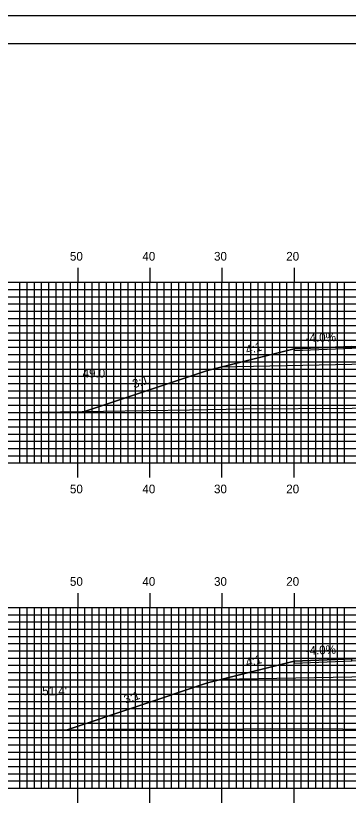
# Model space of a CAD drawing. Extents: x 1822392 to 1822735, y 442591 to 442811.
# Drawn here: x 1822499.2 to 1822545.3, y 442701.2 to 442810.5 of the extents above; entities that cross this region are included whole.
import ezdxf

# ---------------------------------------------------------------- set-up
doc = ezdxf.new("R2010")
doc.units = 0
for name, color, linetype in [('ANNOTATION', 7, 'Continuous'), ('BORDER', 7, 'Continuous'), ('D_Roadway_Centerline', 7, 'Continuous'), ('D_Roadway_Edge_Shoulder', 7, 'Continuous'), ('D_Roadway_SlopeLines', 7, 'Continuous'), ('D_Roadway_SubGrade', 7, 'Continuous'), ('D_Text_Standard', 7, 'Continuous'), ('H_V ANNOTATION', 7, 'Continuous'), ('MAJOR', 7, 'Continuous'), ('MINOR', 7, 'Continuous'), ('PLOT BOUNDARY', 7, 'Continuous'), ('S_Roadway_Centerline', 7, 'Continuous')]:
    doc.layers.add(name, color=color, linetype=linetype)

msp = doc.modelspace()

# ---------------------------------------------------------------- linework, layer by layer
at = {"layer": 'BORDER'}
msp.add_lwpolyline([(1822408.17, 442596.67), (1822728.17, 442596.67), (1822728.17, 442806.67), (1822408.17, 442806.67)], close=True, dxfattribs=at)
at = {"layer": 'D_Roadway_Centerline'}
for points in [[(1822508.73, 442755.8), (1822525.77, 442761.48), (1822527.6, 442761.94), (1822537.77, 442764.48), (1822545.77, 442764.8), (1822557.77, 442765.04), (1822569.77, 442764.8), (1822577.77, 442764.48), (1822587.94, 442761.94), (1822589.77, 442761.48), (1822605.37, 442756.28)], [(1822506.33, 442711.75), (1822525.77, 442718.23), (1822527.6, 442718.69), (1822537.77, 442721.23), (1822545.77, 442721.55), (1822557.77, 442721.79), (1822569.77, 442721.55), (1822577.77, 442721.23), (1822587.94, 442718.69), (1822589.77, 442718.23), (1822609.65, 442711.6)]]:
    msp.add_lwpolyline(points, dxfattribs=at)
at = {"layer": 'D_Roadway_Edge_Shoulder'}
for points in [[(1822545.77, 442764.8), (1822537.77, 442764.48), (1822537.77, 442764.23), (1822545.77, 442764.55)], [(1822545.77, 442721.55), (1822537.77, 442721.23), (1822537.77, 442720.98), (1822545.77, 442721.3)]]:
    msp.add_lwpolyline(points, close=True, dxfattribs=at)
at = {"layer": 'D_Roadway_SlopeLines'}
for points in [[(1822537.77, 442764.48), (1822525.77, 442761.48), (1822508.73, 442755.8)], [(1822537.77, 442721.23), (1822525.77, 442718.23), (1822506.33, 442711.75)]]:
    msp.add_lwpolyline(points, dxfattribs=at)
at = {"layer": 'D_Roadway_SubGrade'}
for points in [[(1822545.77, 442762.3), (1822527.6, 442761.94), (1822537.77, 442764.48), (1822537.77, 442764.23), (1822545.77, 442764.55), (1822557.77, 442764.79), (1822569.77, 442764.55), (1822577.77, 442764.23), (1822577.77, 442764.48), (1822587.94, 442761.94), (1822569.77, 442762.3), (1822557.77, 442762.54)], [(1822545.77, 442719.05), (1822527.6, 442718.69), (1822537.77, 442721.23), (1822537.77, 442720.98), (1822545.77, 442721.3), (1822557.77, 442721.54), (1822569.77, 442721.3), (1822577.77, 442720.98), (1822577.77, 442721.23), (1822587.94, 442718.69), (1822569.77, 442719.05), (1822557.77, 442719.29)]]:
    msp.add_lwpolyline(points, close=True, dxfattribs=at)
at = {"layer": 'MAJOR'}
for p, q in [((1822507.77, 442775.67), (1822507.77, 442773.67)), ((1822517.77, 442775.67), (1822517.77, 442773.67)), ((1822527.77, 442775.67), (1822527.77, 442773.67)), ((1822537.77, 442775.67), (1822537.77, 442773.67)), ((1822417.77, 442773.67), (1822697.77, 442773.67)), ((1822417.77, 442773.67), (1822697.77, 442773.67)), ((1822507.77, 442748.67), (1822507.77, 442773.67)), ((1822517.77, 442748.67), (1822517.77, 442773.67)), ((1822527.77, 442748.67), (1822527.77, 442773.67)), ((1822537.77, 442748.67), (1822537.77, 442773.67)), ((1822417.77, 442768.67), (1822697.77, 442768.67)), ((1822417.77, 442763.67), (1822697.77, 442763.67)), ((1822417.77, 442758.67), (1822697.77, 442758.67)), ((1822417.77, 442753.67), (1822697.77, 442753.67)), ((1822417.77, 442748.67), (1822697.77, 442748.67)), ((1822417.77, 442748.67), (1822697.77, 442748.67)), ((1822507.77, 442746.66), (1822507.77, 442748.67)), ((1822517.77, 442746.66), (1822517.77, 442748.67)), ((1822527.77, 442746.66), (1822527.77, 442748.67)), ((1822537.77, 442746.66), (1822537.77, 442748.67)), ((1822507.77, 442730.67), (1822507.77, 442728.67)), ((1822517.77, 442730.67), (1822517.77, 442728.67)), ((1822527.77, 442730.67), (1822527.77, 442728.67)), ((1822537.77, 442730.67), (1822537.77, 442728.67)), ((1822417.77, 442728.67), (1822697.77, 442728.67)), ((1822417.77, 442728.67), (1822697.77, 442728.67)), ((1822507.77, 442703.67), (1822507.77, 442728.67)), ((1822517.77, 442703.67), (1822517.77, 442728.67)), ((1822527.77, 442703.67), (1822527.77, 442728.67)), ((1822537.77, 442703.67), (1822537.77, 442728.67)), ((1822417.77, 442723.67), (1822697.77, 442723.67)), ((1822417.77, 442718.67), (1822697.77, 442718.67)), ((1822417.77, 442713.67), (1822697.77, 442713.67)), ((1822417.77, 442708.67), (1822697.77, 442708.67)), ((1822417.77, 442703.67), (1822697.77, 442703.67)), ((1822417.77, 442703.67), (1822697.77, 442703.67)), ((1822507.77, 442701.66), (1822507.77, 442703.67)), ((1822517.77, 442701.66), (1822517.77, 442703.67)), ((1822527.77, 442701.66), (1822527.77, 442703.67)), ((1822537.77, 442701.66), (1822537.77, 442703.67))]:
    msp.add_line(p, q, dxfattribs=at)
at = {"layer": 'MINOR'}
for p, q in [((1822499.77, 442748.67), (1822499.77, 442773.67)), ((1822500.77, 442748.67), (1822500.77, 442773.67)), ((1822501.77, 442748.67), (1822501.77, 442773.67)), ((1822502.77, 442748.67), (1822502.77, 442773.67)), ((1822503.77, 442748.67), (1822503.77, 442773.67)), ((1822504.77, 442748.67), (1822504.77, 442773.67)), ((1822505.77, 442748.67), (1822505.77, 442773.67)), ((1822506.77, 442748.67), (1822506.77, 442773.67)), ((1822508.77, 442748.67), (1822508.77, 442773.67)), ((1822509.77, 442748.67), (1822509.77, 442773.67)), ((1822510.77, 442748.67), (1822510.77, 442773.67)), ((1822511.77, 442748.67), (1822511.77, 442773.67)), ((1822512.77, 442748.67), (1822512.77, 442773.67)), ((1822513.77, 442748.67), (1822513.77, 442773.67)), ((1822514.77, 442748.67), (1822514.77, 442773.67)), ((1822515.77, 442748.67), (1822515.77, 442773.67)), ((1822516.77, 442748.67), (1822516.77, 442773.67)), ((1822518.77, 442748.67), (1822518.77, 442773.67)), ((1822519.77, 442748.67), (1822519.77, 442773.67)), ((1822520.77, 442748.67), (1822520.77, 442773.67)), ((1822521.77, 442748.67), (1822521.77, 442773.67)), ((1822522.77, 442748.67), (1822522.77, 442773.67)), ((1822523.77, 442748.67), (1822523.77, 442773.67)), ((1822524.77, 442748.67), (1822524.77, 442773.67)), ((1822525.77, 442748.67), (1822525.77, 442773.67)), ((1822526.77, 442748.67), (1822526.77, 442773.67)), ((1822528.77, 442748.67), (1822528.77, 442773.67)), ((1822529.77, 442748.67), (1822529.77, 442773.67)), ((1822530.77, 442748.67), (1822530.77, 442773.67)), ((1822531.77, 442748.67), (1822531.77, 442773.67)), ((1822532.77, 442748.67), (1822532.77, 442773.67)), ((1822533.77, 442748.67), (1822533.77, 442773.67)), ((1822534.77, 442748.67), (1822534.77, 442773.67)), ((1822535.77, 442748.67), (1822535.77, 442773.67)), ((1822536.77, 442748.67), (1822536.77, 442773.67)), ((1822538.77, 442748.67), (1822538.77, 442773.67)), ((1822539.77, 442748.67), (1822539.77, 442773.67)), ((1822540.77, 442748.67), (1822540.77, 442773.67)), ((1822541.77, 442748.67), (1822541.77, 442773.67)), ((1822542.77, 442748.67), (1822542.77, 442773.67)), ((1822543.77, 442748.67), (1822543.77, 442773.67)), ((1822544.77, 442748.67), (1822544.77, 442773.67)), ((1822417.77, 442772.67), (1822697.77, 442772.67)), ((1822417.77, 442771.67), (1822697.77, 442771.67)), ((1822417.77, 442770.67), (1822697.77, 442770.67)), ((1822417.77, 442769.67), (1822697.77, 442769.67)), ((1822417.77, 442767.67), (1822697.77, 442767.67)), ((1822417.77, 442766.67), (1822697.77, 442766.67)), ((1822417.77, 442765.67), (1822697.77, 442765.67)), ((1822417.77, 442764.67), (1822697.77, 442764.67)), ((1822417.77, 442762.67), (1822697.77, 442762.67)), ((1822417.77, 442761.67), (1822697.77, 442761.67)), ((1822417.77, 442760.67), (1822697.77, 442760.67)), ((1822417.77, 442759.67), (1822697.77, 442759.67)), ((1822417.77, 442757.67), (1822697.77, 442757.67)), ((1822417.77, 442756.67), (1822697.77, 442756.67)), ((1822417.77, 442755.67), (1822697.77, 442755.67)), ((1822417.77, 442754.67), (1822697.77, 442754.67)), ((1822417.77, 442752.67), (1822697.77, 442752.67)), ((1822417.77, 442751.67), (1822697.77, 442751.67)), ((1822417.77, 442750.67), (1822697.77, 442750.67)), ((1822417.77, 442749.67), (1822697.77, 442749.67)), ((1822499.77, 442703.67), (1822499.77, 442728.67)), ((1822500.77, 442703.67), (1822500.77, 442728.67)), ((1822501.77, 442703.67), (1822501.77, 442728.67)), ((1822502.77, 442703.67), (1822502.77, 442728.67)), ((1822503.77, 442703.67), (1822503.77, 442728.67)), ((1822504.77, 442703.67), (1822504.77, 442728.67)), ((1822505.77, 442703.67), (1822505.77, 442728.67)), ((1822506.77, 442703.67), (1822506.77, 442728.67)), ((1822508.77, 442703.67), (1822508.77, 442728.67)), ((1822509.77, 442703.67), (1822509.77, 442728.67)), ((1822510.77, 442703.67), (1822510.77, 442728.67)), ((1822511.77, 442703.67), (1822511.77, 442728.67)), ((1822512.77, 442703.67), (1822512.77, 442728.67)), ((1822513.77, 442703.67), (1822513.77, 442728.67)), ((1822514.77, 442703.67), (1822514.77, 442728.67)), ((1822515.77, 442703.67), (1822515.77, 442728.67)), ((1822516.77, 442703.67), (1822516.77, 442728.67)), ((1822518.77, 442703.67), (1822518.77, 442728.67)), ((1822519.77, 442703.67), (1822519.77, 442728.67)), ((1822520.77, 442703.67), (1822520.77, 442728.67)), ((1822521.77, 442703.67), (1822521.77, 442728.67)), ((1822522.77, 442703.67), (1822522.77, 442728.67)), ((1822523.77, 442703.67), (1822523.77, 442728.67)), ((1822524.77, 442703.67), (1822524.77, 442728.67)), ((1822525.77, 442703.67), (1822525.77, 442728.67)), ((1822526.77, 442703.67), (1822526.77, 442728.67)), ((1822528.77, 442703.67), (1822528.77, 442728.67)), ((1822529.77, 442703.67), (1822529.77, 442728.67)), ((1822530.77, 442703.67), (1822530.77, 442728.67)), ((1822531.77, 442703.67), (1822531.77, 442728.67)), ((1822532.77, 442703.67), (1822532.77, 442728.67)), ((1822533.77, 442703.67), (1822533.77, 442728.67)), ((1822534.77, 442703.67), (1822534.77, 442728.67)), ((1822535.77, 442703.67), (1822535.77, 442728.67)), ((1822536.77, 442703.67), (1822536.77, 442728.67)), ((1822538.77, 442703.67), (1822538.77, 442728.67)), ((1822539.77, 442703.67), (1822539.77, 442728.67)), ((1822540.77, 442703.67), (1822540.77, 442728.67)), ((1822541.77, 442703.67), (1822541.77, 442728.67)), ((1822542.77, 442703.67), (1822542.77, 442728.67)), ((1822543.77, 442703.67), (1822543.77, 442728.67)), ((1822544.77, 442703.67), (1822544.77, 442728.67)), ((1822417.77, 442727.67), (1822697.77, 442727.67)), ((1822417.77, 442726.67), (1822697.77, 442726.67)), ((1822417.77, 442725.67), (1822697.77, 442725.67)), ((1822417.77, 442724.67), (1822697.77, 442724.67)), ((1822417.77, 442722.67), (1822697.77, 442722.67)), ((1822417.77, 442721.67), (1822697.77, 442721.67)), ((1822417.77, 442720.67), (1822697.77, 442720.67)), ((1822417.77, 442719.67), (1822697.77, 442719.67)), ((1822417.77, 442717.67), (1822697.77, 442717.67)), ((1822417.77, 442716.67), (1822697.77, 442716.67)), ((1822417.77, 442715.67), (1822697.77, 442715.67)), ((1822417.77, 442714.67), (1822697.77, 442714.67)), ((1822417.77, 442712.67), (1822697.77, 442712.67)), ((1822417.77, 442711.67), (1822697.77, 442711.67)), ((1822417.77, 442710.67), (1822697.77, 442710.67)), ((1822417.77, 442709.67), (1822697.77, 442709.67)), ((1822417.77, 442707.67), (1822697.77, 442707.67)), ((1822417.77, 442706.67), (1822697.77, 442706.67)), ((1822417.77, 442705.67), (1822697.77, 442705.67)), ((1822417.77, 442704.67), (1822697.77, 442704.67))]:
    msp.add_line(p, q, dxfattribs=at)
at = {"layer": 'PLOT BOUNDARY'}
msp.add_lwpolyline([(1822391.98, 442590.55), (1822731.98, 442590.55), (1822731.98, 442810.55), (1822391.98, 442810.55)], close=True, dxfattribs=at)
at = {"layer": 'S_Roadway_Centerline'}
for points in [[(1822497.4, 442755.69), (1822499.43, 442755.66), (1822523.29, 442756.01), (1822530.91, 442756.15), (1822545.83, 442756.25), (1822548.9, 442756.28), (1822550.61, 442756.31), (1822557.81, 442756.47), (1822563.81, 442756.6), (1822565.09, 442756.56), (1822567.47, 442756.54), (1822582.16, 442756.38), (1822590.83, 442756.38), (1822599.22, 442756.28), (1822603.75, 442756.31), (1822616.29, 442756.06)], [(1822498.65, 442711.71), (1822510.54, 442711.77), (1822511.96, 442711.81), (1822521.66, 442711.9), (1822527.19, 442711.81), (1822534.45, 442711.91), (1822544.54, 442711.9), (1822561.61, 442711.7), (1822561.66, 442711.7), (1822561.69, 442711.7), (1822561.82, 442711.7), (1822574.76, 442711.61), (1822578.21, 442711.64), (1822588.42, 442711.63), (1822594.9, 442711.55), (1822606.95, 442711.61), (1822611.99, 442711.6), (1822626.12, 442711.58)]]:
    msp.add_lwpolyline(points, dxfattribs=at)

# ---------------------------------------------------------------- texts
at = {"layer": 'ANNOTATION'}
for s, rotation, p in [('-4.0%', 2.2906, (1822539.4, 442765.35)), ('4:1', 14.0362, (1822531.22, 442763.7)), ('3:1', 18.4348, (1822515.59, 442758.99)), ('-4.0%', 2.2906, (1822539.4, 442722.1)), ('4:1', 14.0362, (1822531.22, 442720.45)), ('3:1', 18.4348, (1822514.39, 442715.34))]:
    msp.add_text(s, height=1.2, rotation=rotation, dxfattribs=at).set_placement(p)
at = {"layer": 'D_Text_Standard'}
for s, p in [("49.0'", (1822508.45, 442760.49)), ("51.4'", (1822502.86, 442716.53))]:
    msp.add_text(s, height=1.2, dxfattribs=at).set_placement(p)
at = {"layer": 'H_V ANNOTATION'}
for s, p in [('50', (1822506.7, 442776.67)), ('40', (1822516.74, 442776.67)), ('30', (1822526.67, 442776.67)), ('20', (1822536.68, 442776.67)), ('50', (1822506.7, 442744.47)), ('40', (1822516.74, 442744.47)), ('30', (1822526.67, 442744.47)), ('20', (1822536.68, 442744.47)), ('50', (1822506.7, 442731.67)), ('40', (1822516.74, 442731.67)), ('30', (1822526.67, 442731.67)), ('20', (1822536.68, 442731.67))]:
    msp.add_text(s, height=1.2, dxfattribs=at).set_placement(p)

doc.saveas('drawing.dxf')
